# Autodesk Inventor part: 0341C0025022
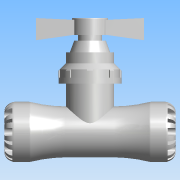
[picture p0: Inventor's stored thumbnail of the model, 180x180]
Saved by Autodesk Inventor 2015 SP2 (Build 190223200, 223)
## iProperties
Created: 2016-12
Part Number: 0341C0025022
Material: PVC-Piping
Description: PLASSON COPPER PIPE ADAPTOR STOPTAP 25-22 SERIES 1
Document SubType Name: Modeling
Designer: KIM
Mass: 61.7504 g
Surface Area: 140.097 cm^2
Volume: 44.1074 cm^3
Density: 1.4 g/cm^3
Appearance: Smooth - White
Author: KIM
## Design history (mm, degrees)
derived "0341C.ipt"
feature "Solid1::0341C.ipt"
feature "Solid2::0341C.ipt"
tag "TaggingFeature1"
body "Solid1"
other parameters: "d1" = 20.16, "d2" = 25, "d3" = 31.25, "d4" = 47, "d6" = 48, "d8" = 39.95, "d13" = 6.3, "d14" = 6.3, "d15" = 0, "d17" = 360 deg, "d19" = 8 deg, "d20" = 0.5, "d21" = 0.5, "d22" = 8 deg, "d24" = 0, "d26" = 360 deg, "d33" = 4.7, "d35" = 3.125, "d65" = 0.47, "d69" = 134, "d71" = 22, "d72" = 47, "d73" = 31.25, "d74" = 20.16, "d75" = 67, "d76" = 2.75, "d77" = 48, "d80" = 6.3, "d82" = 6.3, "d83" = 0, "d85" = 360 deg, "d87" = 0.44, "d88" = 8 deg, "d89" = 8 deg, "d90" = 0.44, "d92" = 0, "d94" = 360 deg, "d96" = 89, "d97" = 47, "d98" = 37.6, "d99" = 37.6, "d100" = 135 deg, "d101" = 18.8, "d102" = 70 deg, "d103" = 48.95, "d104" = 71.2, "d105" = 62.3, "d107" = 75.65, "d108" = 84.6, "d110" = 12.015, "d111" = 4.005, "d112" = 14.1, "d113" = 0, "d114" = 49.35, "d115" = 4.7, "d116" = 0, "d117" = 4.7, "d119" = 0, "d121" = 360 deg, "d127" = 0, "d128" = 0.47, "d_" = 25, "E_" = 47, "H_" = 134, "l_" = 48, "A_" = 89, "l_1" = 48, "d_1" = 22, "E_1" = 47, "d9" = 7.875, "d11" = 47, "d12" = 31.25, "d78" = 47, "d79" = 31.25, "d81" = 7.875, "d109" = 13.35
